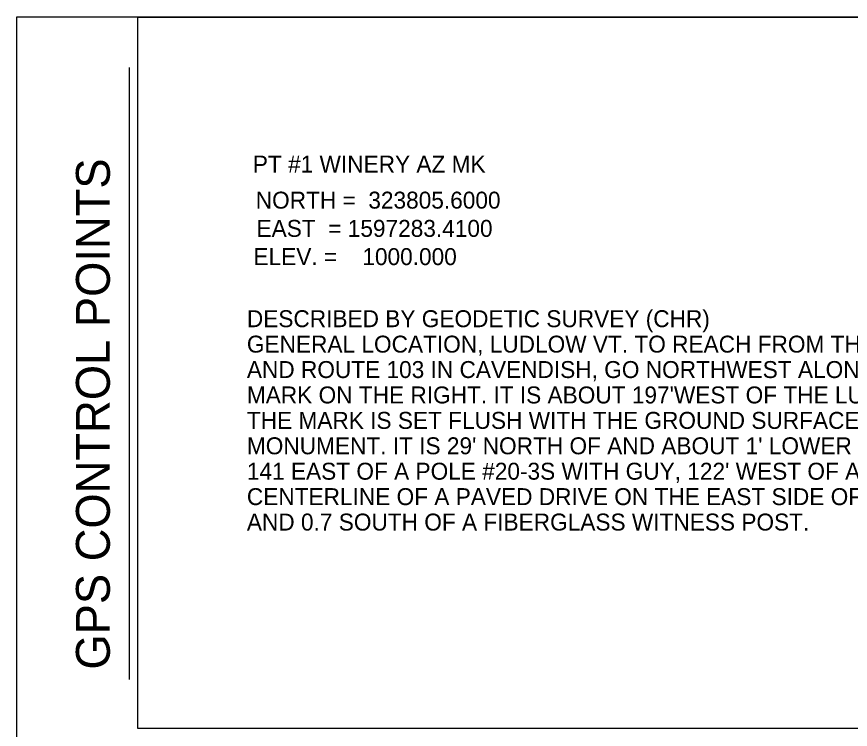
# Model space of a CAD drawing. Extents: x 1603676 to 1604316, y 320315 to 320735.
# Drawn here: x 1603675.9 to 1603823.6, y 320608.4 to 320734.6 of the extents above; entities that cross this region are included whole.
import ezdxf

# ---------------------------------------------------------------- set-up
doc = ezdxf.new("R2010")
doc.units = 0
for name, color, linetype in [('LDEFAULT', 7, 'Continuous'), ('NBL1', 7, 'Continuous'), ('NBL2', 7, 'Continuous')]:
    doc.layers.add(name, color=color, linetype=linetype)

msp = doc.modelspace()

# ---------------------------------------------------------------- linework, layer by layer
at = {"layer": 'NBL1'}
for p, q in [((1603697.37, 320608.58), (1603697.37, 320734.48)), ((1603697.37, 320734.48), (1604315.12, 320734.48)), ((1603695.93, 320617.23), (1603695.93, 320725.57)), ((1604315.12, 320608.58), (1603697.37, 320608.58))]:
    msp.add_line(p, q, dxfattribs=at)
msp.add_lwpolyline([(1604315.93, 320314.57), (1603675.93, 320314.57), (1603675.93, 320734.57), (1604315.93, 320734.57)], close=True, dxfattribs=at)

# ---------------------------------------------------------------- texts
at = {"layer": 'LDEFAULT'}
for s, p in [('DESCRIBED BY GEODETIC SURVEY (CHR)', (1603716.71, 320679.6)), ('GENERAL LOCATION, LUDLOW VT. TO REACH FROM THE INTERSECTION OF SCENIC VT ROUTE 131 ', (1603716.71, 320675.1)), ('AND ROUTE 103 IN CAVENDISH, GO NORTHWEST ALONG ROUTE 103 FOR 0.9 MI TO THE SITE OF THE ', (1603716.71, 320670.6)), ("MARK ON THE RIGHT. IT IS ABOUT 197'WEST OF THE LUDLOW/CAVENDISH TOWN LINE. ", (1603716.71, 320666.1)), ('THE MARK IS SET FLUSH WITH THE GROUND SURFACE IN THE TOP OF A 12" DIAMETER CONCRETE ', (1603716.71, 320661.6)), ("MONUMENT. IT IS 29' NORTH OF AND ABOUT 1' LOWER THAN THE CENTERLINE OF ROUTE 103, ", (1603716.71, 320657.1)), ('141 EAST OF A POLE #20-3S WITH GUY, 122\' WEST OF A 20" OAK, 160\'EAST OF THE ', (1603716.71, 320652.6)), ('CENTERLINE OF A PAVED DRIVE ON THE EAST SIDE OF FLETCHER FARMS COMPOUND, ', (1603716.71, 320648.1)), ('AND 0.7 SOUTH OF A FIBERGLASS WITNESS POST.', (1603716.71, 320643.6))]:
    msp.add_text(s, height=3, dxfattribs=at).set_placement(p)
at = {"layer": 'NBL1'}
msp.add_text('GPS CONTROL POINTS', height=6, rotation=90, dxfattribs=at).set_placement((1603692.43, 320618.98))
at = {"layer": 'NBL2'}
for s, p in [('PT #1 WINERY AZ MK  ', (1603717.77, 320706.97)), ('NORTH =  323805.6000', (1603718.28, 320700.59)), ('EAST  = 1597283.4100', (1603718.42, 320695.59)), ('ELEV. =    1000.000 ', (1603717.88, 320690.59))]:
    msp.add_text(s, height=3, dxfattribs=at).set_placement(p)

doc.saveas('drawing.dxf')
